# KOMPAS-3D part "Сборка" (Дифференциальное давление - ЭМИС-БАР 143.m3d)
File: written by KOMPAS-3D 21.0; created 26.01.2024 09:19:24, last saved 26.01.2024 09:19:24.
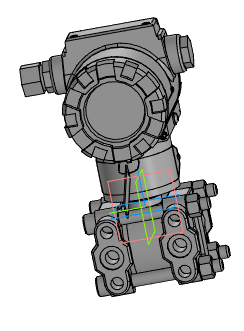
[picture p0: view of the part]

Document properties: Автор: Admin; Организация: office.local; Полное имя файла: S:\Эмис\Инженерный\Расходомеры и фильтры\Задачи\Черненков А.А\ЭМИС-БАР\3D-модели для сайта\Датчики дифференциального давления ЭМИС-БАР\Компоненты\ЭМИС-БАР 143.m3d

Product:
- Part/product: Сборка
    Масса: 6.880233

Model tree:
1. Операция без истории:1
